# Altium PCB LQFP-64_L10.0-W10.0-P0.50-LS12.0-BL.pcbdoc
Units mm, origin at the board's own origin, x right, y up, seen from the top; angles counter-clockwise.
Board outline 25.6 x 25.61 mm, 2 copper layers (Top Layer, Bottom Layer), stack 0.07 mm thick; 1 components, 0 nets, 64 pads, 0 vias.
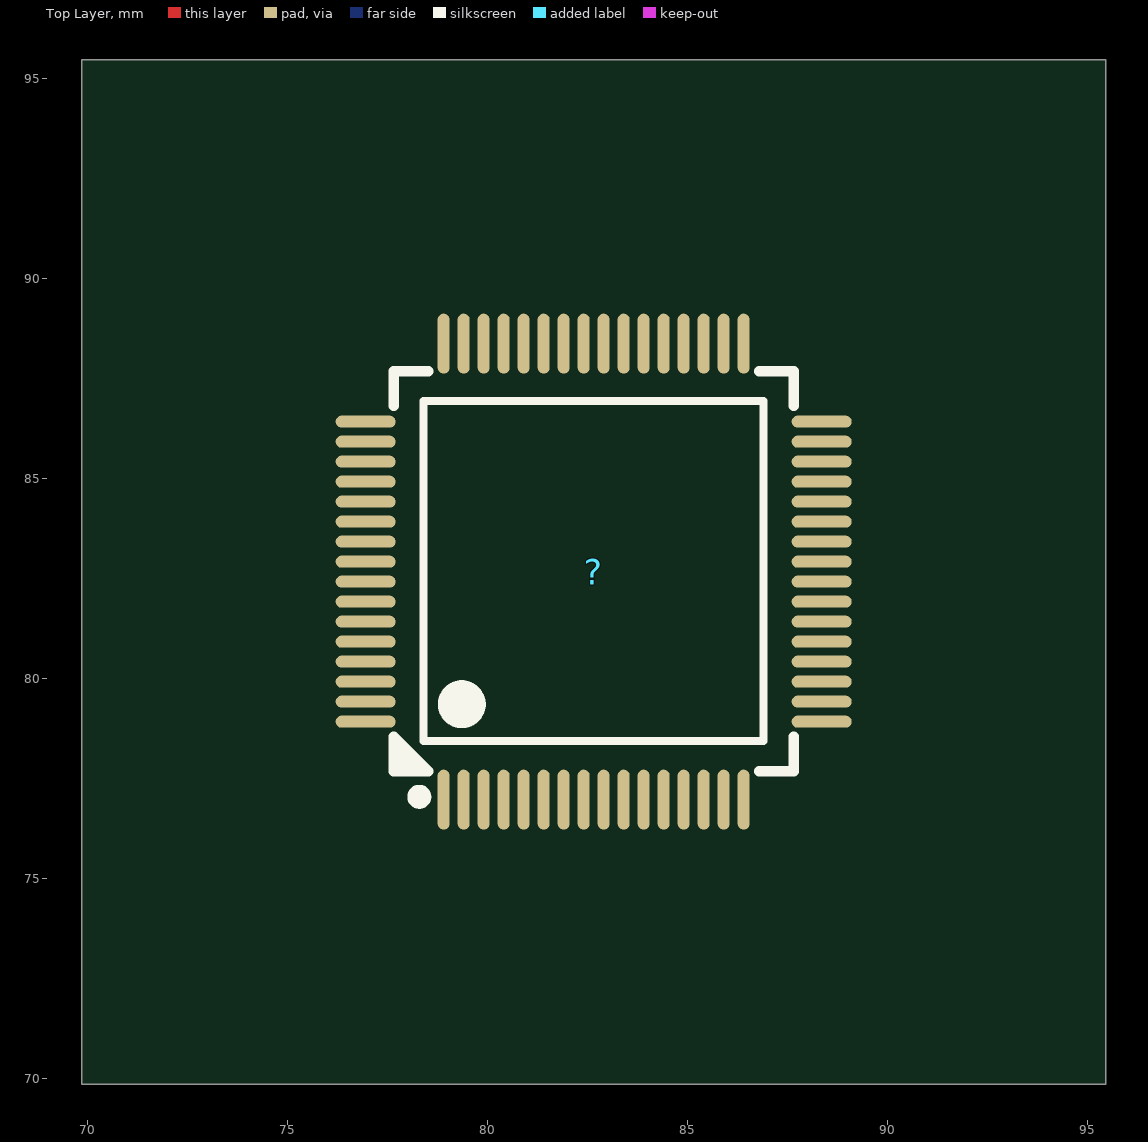
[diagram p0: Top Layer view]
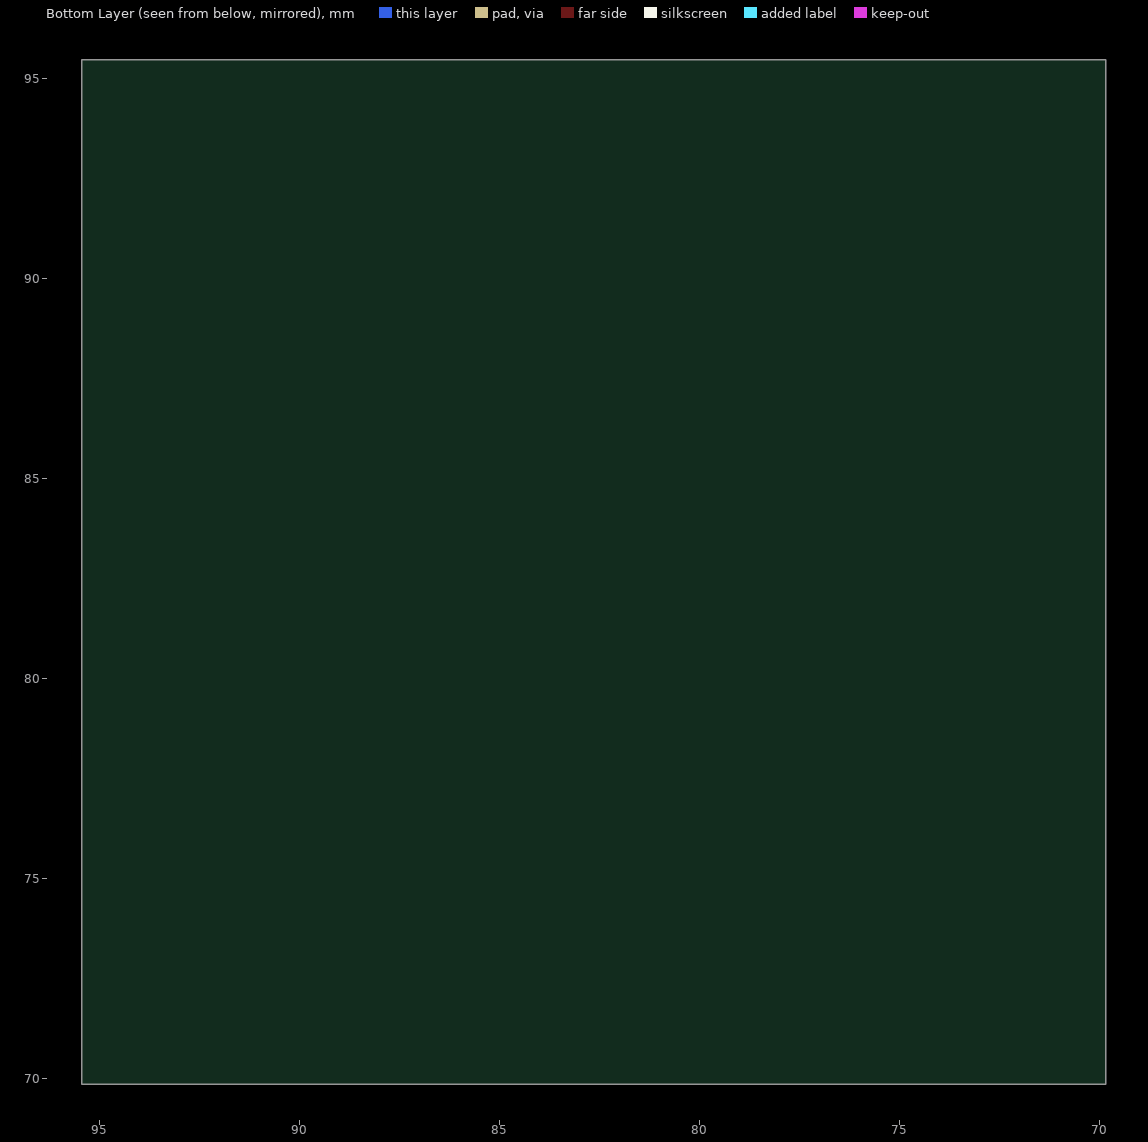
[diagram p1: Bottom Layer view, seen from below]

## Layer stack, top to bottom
Top Solder Mask Layer: solder mask 0.01, Dk 3.3
Top Layer: signal copper 0.035
Bottom Layer: signal copper 0.035
Bottom Solder Mask Layer: solder mask 0.01, Dk 3.3

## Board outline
95.45,69.85 69.85,69.85 69.85,95.458 95.45,95.458

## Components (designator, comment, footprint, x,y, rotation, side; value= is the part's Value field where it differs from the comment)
? "LQFP-64_L10.0-W10.0-P0.50-LS12.0-BL" LQFP-64_L10.0-W10.0-P0.50-LS12.0-BL 82.65,82.658 r0 top

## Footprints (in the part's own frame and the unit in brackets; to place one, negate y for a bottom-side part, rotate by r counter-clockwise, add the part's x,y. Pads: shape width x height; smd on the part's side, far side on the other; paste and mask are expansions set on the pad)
LQFP-64_L10.0-W10.0-P0.50-LS12.0-BL [mm]
  oval 0.3x1.5 smd paste+0 mask+0.051: 1(-3.75,-5.7) 2(-3.25,-5.7) 3(-2.75,-5.7) 4(-2.25,-5.7) 5(-1.75,-5.7) 6(-1.25,-5.7) 7(-0.75,-5.7) 8(-0.25,-5.7) 9(0.25,-5.7) 10(0.75,-5.7) 11(1.25,-5.7) 12(1.75,-5.7) 13(2.25,-5.7) 14(2.75,-5.7) 15(3.25,-5.7) 16(3.75,-5.7) 33(3.75,5.7) 34(3.25,5.7) 35(2.75,5.7) 36(2.25,5.7) 37(1.75,5.7) 38(1.25,5.7) 39(0.75,5.7) 40(0.25,5.7) 41(-0.25,5.7) 42(-0.75,5.7) 43(-1.25,5.7) 44(-1.75,5.7) 45(-2.25,5.7) 46(-2.75,5.7) 47(-3.25,5.7) 48(-3.75,5.7)
  oval 1.5x0.3 smd paste+0 mask+0.051: 17(5.7,-3.75) 18(5.7,-3.25) 19(5.7,-2.75) 20(5.7,-2.25) 21(5.7,-1.75) 22(5.7,-1.25) 23(5.7,-0.75) 24(5.7,-0.25) 25(5.7,0.25) 26(5.7,0.75) 27(5.7,1.25) 28(5.7,1.75) 29(5.7,2.25) 30(5.7,2.75) 31(5.7,3.25) 32(5.7,3.75) 49(-5.7,3.75) 50(-5.7,3.25) 51(-5.7,2.75) 52(-5.7,2.25) 53(-5.7,1.75) 54(-5.7,1.25) 55(-5.7,0.75) 56(-5.7,0.25) 57(-5.7,-0.25) 58(-5.7,-0.75) 59(-5.7,-1.25) 60(-5.7,-1.75) 61(-5.7,-2.25) 62(-5.7,-2.75) 63(-5.7,-3.25) 64(-5.7,-3.75)
  silkscreen extent -5,-5.78 5,5.01

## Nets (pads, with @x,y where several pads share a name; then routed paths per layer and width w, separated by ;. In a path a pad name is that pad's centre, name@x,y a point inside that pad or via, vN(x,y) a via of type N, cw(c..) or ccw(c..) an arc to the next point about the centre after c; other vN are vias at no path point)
pads on no net: ?.1 ?.2 ?.3 ?.4 ?.5 ?.6 ?.7 ?.8 ?.9 ?.10 ?.11 ?.12 ?.13 ?.14 ?.15 ?.16 ?.17 ?.18 ?.19 ?.20 ?.21 ?.22 ?.23 ?.24 ?.25 ?.26 ?.27 ?.28 ?.29 ?.30 ?.31 ?.32 ?.33 ?.34 ?.35 ?.36 ?.37 ?.38 ?.39 ?.40 ?.41 ?.42 ?.43 ?.44 ?.45 ?.46 ?.47 ?.48 ?.49 ?.50 ?.51 ?.52 ?.53 ?.54 ?.55 ?.56 ?.57 ?.58 ?.59 ?.60 ?.61 ?.62 ?.63 ?.64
